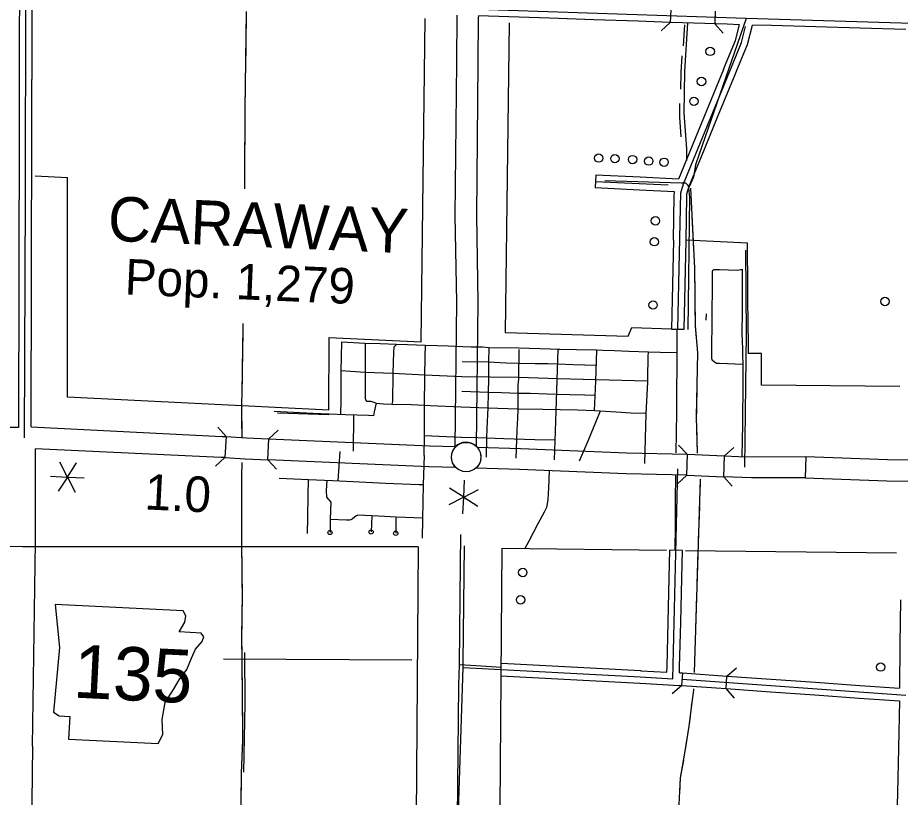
# Model space of a CAD drawing. Extents: x -4306 to 3843, y 131 to 8341.
# Drawn here: x -255 to 1424, y 2952 to 4435 of the extents above; entities that cross this region are included whole.
import ezdxf

# ---------------------------------------------------------------- set-up
doc = ezdxf.new("R2010")
doc.units = 0
for name, color, linetype in [('10', 7, 'Continuous'), ('21', 7, 'Continuous'), ('24', 7, 'Continuous'), ('31', 7, 'Continuous'), ('32', 7, 'Continuous'), ('33', 7, 'Continuous'), ('38', 7, 'Continuous'), ('52', 7, 'Continuous'), ('53', 7, 'Continuous'), ('55', 7, 'Continuous'), ('56', 7, 'Continuous'), ('57', 7, 'Continuous'), ('61', 7, 'Continuous'), ('62', 7, 'Continuous')]:
    doc.layers.add(name, color=color, linetype=linetype)

msp = doc.modelspace()

# ---------------------------------------------------------------- linework, layer by layer
at = {"layer": '10'}
for p, q in [((-252.8, 3655.5), (-600.7, 3657.9)), ((141.8, 3638.2), (139.4, 3598.3)), ((141.9, 3638.2), (180.4, 3636)), ((180.4, 3636), (222.3, 3634.2)), ((221.4, 3594.2), (223.1, 3634.1)), ((-220.3, 3437.9), (-220.6, 3615.3)), ((139.3, 3598.3), (178.3, 3596)), ((178.3, 3596), (221.6, 3594.2)), ((1018.3, 3604.8), (1017.4, 3564.8)), ((1018.8, 3604.8), (1019.4, 3604.8)), ((1019.4, 3604.8), (1088.9, 3601.8)), ((1088.1, 3561.8), (1089.8, 3601.7)), ((1244.5, 3599.9), (1243, 3559.9)), ((1244.5, 3599.9), (1243, 3559.9)), ((1018.2, 3564.8), (1087.9, 3561.8)), ((-226.6, 3049.5), (-220.3, 3437.9))]:
    msp.add_line(p, q, dxfattribs=at)
for points in [[(577.7, 4058.2), (580.3, 4349.6), (581.5, 4439.7)], [(621.4, 4434.2), (620.3, 4349.1), (617.7, 4058.9)], [(621.5, 4438.2), (621.4, 4434.2)], [(577.5, 3619.1), (580.3, 3893.9), (577.7, 4058.2)], [(617.7, 4058.9), (620.3, 3894), (617.5, 3620.2)], [(-228.8, 3656.8), (134.2, 3638.7), (141.9, 3638.2)], [(222.3, 3634.2), (529.3, 3621)], [(139.3, 3598.3), (132.1, 3598.7), (-220.6, 3615.3)], [(529.1, 3621), (578, 3619.5)], [(619.7, 3618.1), (701.5, 3615.5), (903.8, 3607.5), (1018.5, 3604.8)], [(527.6, 3581.1), (221.6, 3594.2)], [(1088.9, 3601.8), (1116.1, 3600.6)], [(1116.1, 3600.6), (1244.5, 3599.9)], [(1819.6, 3589.7), (1570.2, 3591.9), (1399.5, 3594.1), (1244.5, 3599.9)], [(577.7, 3579.5), (527.8, 3581.1)], [(1018.2, 3564.8), (1018.1, 3564.8), (902.5, 3567.5), (700, 3575.5), (617.3, 3578.2)], [(1140.7, 3560), (1087.9, 3561.8)], [(1243, 3559.9), (1140.7, 3560)], [(1243, 3559.9), (1398.5, 3554.1), (1569.7, 3551.9), (1817.9, 3549.8)], [(-226.6, 3049.5), (-229, 2837.2)]]:
    msp.add_lwpolyline(points, dxfattribs=at)
for centre, radius, start, end in [((598.1, 3598.2), 29.3, 48.5826, 134.7506), ((599.7, 3599.3), 29.6, 137.0643, 221.959), ((598.5, 3599.3), 28.3, 311.6906, 41.5462)]:
    msp.add_arc(centre, radius, start, end, dxfattribs=at)
at = {"layer": '21'}
msp.add_lwpolyline([(-183.1, 3319.2), (-174.9, 3237.4), (-186.4, 3114.7), (-175.9, 3107.4), (-155.6, 3106.4), (-157.7, 3063.1), (12.6, 3054.8), (21.6, 3072), (20.3, 3100.5), (25.9, 3132.8), (42.1, 3157.7), (52.5, 3176.2), (67, 3195.8), (76.1, 3217), (83.8, 3234.3), (96.6, 3248.6), (99.8, 3257.9), (94.7, 3264.9), (52.8, 3267), (63.2, 3285.4), (65.2, 3297.5), (60, 3307.1)], close=True, dxfattribs=at)
at = {"layer": '24'}
msp.add_circle((598.4, 3599.4), 28, dxfattribs=at)
at = {"layer": '31'}
for p, q in [((-251.3, 4474.7), (-251.4, 4402.1)), ((-227.3, 4474), (-227.4, 4402)), ((1110.5, 4391.4), (1118.2, 4421.4)), ((1121.9, 4387.6), (1129.7, 4418)), ((1133.3, 4383.8), (1142.8, 4420.7)), ((-251.4, 4402.1), (-251.6, 4317.6)), ((-227.4, 4402), (-227.6, 4317.5)), ((1092.8, 4348.6), (1110.5, 4391.4)), ((1103.9, 4344), (1121.9, 4387.6)), ((1115, 4339.4), (1133.3, 4383.8)), ((1087.6, 4336), (1092.8, 4348.6)), ((1011.3, 4118.6), (1103.9, 4344)), ((1087.6, 4336), (1087.6, 4336)), ((1109.8, 4326.9), (1115, 4339.4)), ((1022.6, 4114.6), (1045.6, 4170.6)), ((844.7, 4135.6), (843.5, 4111.6)), ((844.1, 4123.6), (982.6, 4116.8)), ((1006.2, 4101.9), (1011.3, 4118.6)), ((1018.2, 4100), (1022.6, 4114.6)), ((-240, 4096.4), (-242, 3636.2)), ((992.4, 4011.8), (994.1, 4096.2)), ((994.1, 4096.2), (994.2, 4103.8)), ((1001, 3842.6), (1006.2, 4101.9)), ((1016.4, 4011.3), (1018.1, 4095.7)), ((1018.1, 4095.7), (1018.2, 4100)), ((1054.8, 3871.6), (1054, 3859.8)), ((989, 3842.8), (1012.9, 3842.3)), ((239.5, 3683.8), (337.1, 3680.5))]:
    msp.add_line(p, q, dxfattribs=at)
for points in [[(1087.6, 4336), (1055.5, 4257.9)], [(-251.6, 4317.6), (-251.7, 4233.1)], [(-227.7, 4233), (-227.6, 4317.5)], [(1077.7, 4248.7), (1109.8, 4326.9)], [(1055.5, 4257.9), (1002.1, 4127.9)], [(1045.6, 4170.6), (1077.7, 4248.7)], [(-251.7, 4233.1), (-252.8, 3655.5)], [(-228.8, 3656.8), (-227.7, 4233)], [(929.1, 4131.5), (844.7, 4135.6)], [(1002.1, 4127.9), (929.1, 4131.5)], [(843.5, 4111.6), (927.9, 4107.5)], [(927.9, 4107.5), (994.3, 4104.3)], [(992.4, 4011.8), (990.7, 3927.3)], [(1014.7, 3926.8), (1016.4, 4011.3)], [(990.7, 3927.3), (989, 3842.8)], [(1012.9, 3842.3), (1014.7, 3926.8)], [(579.9, 2808.9), (592.5, 3199.4), (592.3, 3209.3), (595.4, 3430.4)]]:
    msp.add_lwpolyline(points, dxfattribs=at)
at = {"layer": '32'}
for p, q in [((-239.3, 4486.5), (-240, 4096.4)), ((1130.8, 4433), (602.5, 4450.9)), ((987.3, 4449.9), (986.5, 4425.9)), ((756.5, 4433.6), (621.5, 4438.2)), ((841, 4430.8), (756.5, 4433.6)), ((1130.8, 4433), (1041.4, 4175.2)), ((1071.8, 4447), (1071, 4423)), ((1446.4, 4423.8), (1130.8, 4433)), ((925.4, 4427.9), (841, 4430.8)), ((986.5, 4425.9), (925.4, 4427.9)), ((1009.9, 4425.1), (986.5, 4425.9)), ((1094.3, 4422.2), (1009.9, 4425.1)), ((1118.2, 4421.4), (1094.3, 4422.2)), ((1178.8, 4419.6), (1142.8, 4420.7)), ((1263.2, 4417.1), (1178.8, 4419.6)), ((1347.7, 4414.7), (1263.2, 4417.1)), ((1434.2, 4412.2), (1347.7, 4414.7)), ((1041.4, 4175.2), (1034.5, 4154.8)), ((1034.5, 4154.8), (1030.7, 4131.6)), ((1030.7, 4131.6), (1021.8, 4112.2)), ((1007.9, 4120.3), (862, 4124.7)), ((1016.1, 4120.1), (1007.9, 4120.3)), ((1020.2, 4115.4), (1016.1, 4120.1)), ((1021.8, 4112.2), (1020.2, 4115.4)), ((1023.3, 4093), (1021.8, 4112.2)), ((1020.6, 3842.1), (1023.3, 4093)), ((984.2, 3370), (985.4, 3422.3)), ((1009.4, 3421.7), (985.4, 3422.3)), ((1008.1, 3369.4), (1009.4, 3422)), ((982.2, 3285.5), (984.2, 3370)), ((1006.2, 3285), (1008.1, 3369.4)), ((1423.9, 3328.2), (1423.1, 3243.7)), ((980.2, 3201.1), (982.2, 3285.5)), ((1004.2, 3200.5), (1006.2, 3285)), ((1423.1, 3243.7), (1422.3, 3159.9)), ((665, 3207.6), (677.5, 3206.9)), ((677.5, 3206.9), (761.9, 3202.4)), ((761.9, 3202.4), (846.2, 3197.9)), ((846.2, 3197.9), (929.9, 3193.4)), ((929.9, 3193.4), (930.6, 3193.3)), ((930.6, 3193.3), (979.9, 3190.7)), ((979.9, 3190.7), (980.2, 3201.1)), ((1003.9, 3189.5), (1004.2, 3200.5)), ((1003.9, 3189.5), (1009.9, 3189.1)), ((1008.4, 3165.1), (1010.1, 3189.1)), ((1009.9, 3189.1), (1094.2, 3183.1)), ((664.8, 3183.5), (676.2, 3182.9)), ((676.2, 3182.9), (760.6, 3178.4)), ((760.6, 3178.4), (845, 3173.9)), ((845, 3173.9), (928.6, 3169.4)), ((1009.1, 3177.1), (1434.2, 3147)), ((1092.5, 3159.2), (1094.2, 3183.1)), ((1094.2, 3183.1), (1178.5, 3177.1)), ((1178.5, 3177.1), (1262.8, 3171.2)), ((928.6, 3169.4), (929.3, 3169.4)), ((929.3, 3169.4), (1003.3, 3165.4)), ((1003.3, 3165.5), (1008.3, 3165.1)), ((1008.2, 3165.1), (1092.5, 3159.2)), ((1092.5, 3159.2), (1176.8, 3153.2)), ((1262.8, 3171.2), (1347.1, 3165.2)), ((1347.1, 3165.2), (1422.3, 3159.9)), ((1176.8, 3153.2), (1261.1, 3147.2)), ((1261.1, 3147.2), (1345.4, 3141.3)), ((1345.4, 3141.3), (1422.1, 3135.8)), ((1422.1, 3135.8), (1420.1, 3045.8)), ((1420.1, 3045.8), (1418.2, 2961.3)), ((1418.2, 2961.3), (1416.3, 2876.8))]:
    msp.add_line(p, q, dxfattribs=at)
for points in [[(1129.5, 3992.9), (1130.7, 3833.8)], [(1130.7, 3833.8), (1129.6, 3736.4), (1127.8, 3580.1)], [(929.3, 3181.4), (991.6, 3178), (1001, 3577.3)], [(592.5, 3199.4), (929.3, 3181.4)]]:
    msp.add_lwpolyline(points, dxfattribs=at)
at = {"layer": '33'}
for p, q in [((1066.7, 3951.8), (1067.6, 3954.6)), ((1066.7, 3936.2), (1066.7, 3951.8)), ((1067.6, 3954.6), (1069.6, 3956)), ((1069.6, 3956), (1079.9, 3956.3)), ((1079.9, 3956.3), (1114.5, 3955)), ((1114.5, 3955), (1120.1, 3955.7)), ((1120.1, 3955.7), (1122.8, 3956)), ((1123.8, 3875.3), (1123.7, 3956.8)), ((1065.9, 3858.9), (1066.7, 3936.2)), ((1123, 3835.6), (1123.8, 3875.3)), ((1065.5, 3803), (1065.9, 3858.9)), ((999.4, 3775.4), (999.4, 3841.3)), ((1124.5, 3804.4), (1123, 3835.6)), ((361, 3817.6), (360.1, 3763.4)), ((406.1, 3815.4), (361, 3817.6)), ((434.6, 3814.6), (406.1, 3815.4)), ((406.1, 3815.4), (406.2, 3781.4)), ((466, 3813.7), (434.6, 3814.6)), ((466, 3813.7), (461, 3808.4)), ((486.8, 3812.7), (466, 3813.7)), ((521.1, 3811.6), (486.8, 3812.7)), ((520.3, 3790.7), (521.2, 3811.3)), ((564.4, 3810.1), (521.1, 3811.6)), ((591.3, 3809), (564.4, 3810.1)), ((460.3, 3799.6), (459.1, 3758.2)), ((461, 3808.4), (460.3, 3799.6)), ((608.1, 3808.4), (591.3, 3809)), ((629.5, 3808.6), (608.1, 3808.4)), ((641.7, 3807.3), (629.5, 3808.6)), ((641.7, 3807.3), (640.5, 3780.5)), ((698.5, 3806.3), (641.7, 3807.3)), ((698.4, 3747.7), (699.2, 3804)), ((758.3, 3804.4), (698.5, 3806.3)), ((773.3, 3803.9), (758.3, 3804.4)), ((771.6, 3745.4), (773.2, 3803.9)), ((776.7, 3804.2), (773.3, 3803.9)), ((808, 3803), (776.7, 3804.2)), ((846.2, 3802.4), (808, 3803)), ((845.1, 3743.7), (846.8, 3802.4)), ((858.4, 3802.3), (846.2, 3802.4)), ((880.5, 3801.2), (858.4, 3802.3)), ((907.5, 3800.1), (880.5, 3801.2)), ((944.9, 3798.8), (907.5, 3800.1)), ((944.4, 3791.5), (944.9, 3798.8)), ((967.4, 3798.5), (944.9, 3798.8)), ((999.4, 3797.7), (967.4, 3798.5)), ((1065.4, 3787.9), (1065.5, 3803)), ((1125.1, 3765.2), (1124.5, 3804.4)), ((406.2, 3781.4), (406.4, 3760.2)), ((519.9, 3753), (520.3, 3790.7)), ((590.7, 3781.3), (640.4, 3780.2)), ((640.4, 3780.2), (674.2, 3778.6)), ((640.5, 3780.5), (640.5, 3749.5)), ((674.2, 3778.6), (698.3, 3777.9)), ((698.3, 3777.9), (729.2, 3777)), ((729.2, 3777), (753.3, 3777.3)), ((753.3, 3777.3), (771.9, 3776.4)), ((943.7, 3748.7), (944.4, 3791.5)), ((1065.8, 3783.4), (1065.4, 3787.9)), ((1070.5, 3779.6), (1065.8, 3783.4)), ((1074.5, 3777.5), (1070.5, 3779.6)), ((1079.9, 3777.5), (1074.5, 3777.5)), ((1125, 3775.7), (1079.9, 3777.5)), ((360.1, 3763.4), (359.8, 3708.5)), ((406.4, 3760.5), (360.1, 3763.4)), ((406.4, 3760.2), (406, 3711.5)), ((459.1, 3758.2), (406.4, 3760.5)), ((771.9, 3776.4), (801.7, 3775.4)), ((801.7, 3775.4), (845.9, 3774.1)), ((999.4, 3758.1), (999.4, 3775.4)), ((1125.1, 3743.4), (1125.1, 3765.2)), ((459.1, 3758.2), (458, 3704.8)), ((520, 3754.9), (459.1, 3758.2)), ((519.4, 3696.5), (519.9, 3753)), ((590.2, 3751.8), (520, 3754.9)), ((698.6, 3750.7), (590.2, 3751.8)), ((640.5, 3749.5), (640.4, 3720.9)), ((697.3, 3736.3), (698.4, 3747.7)), ((771.7, 3748.3), (698.6, 3750.7)), ((769.4, 3686.8), (771.6, 3745.4)), ((845.2, 3746.1), (771.7, 3748.3)), ((842.2, 3687.8), (845.1, 3743.7)), ((943.6, 3743.5), (845.2, 3746.1)), ((943.6, 3741.6), (943.7, 3748.7)), ((999, 3738.5), (999.4, 3758.1)), ((1124.3, 3661.2), (1125.1, 3743.4)), ((696.9, 3689.1), (697.3, 3736.3)), ((940.3, 3681.3), (943.6, 3741.6)), ((999, 3722.6), (999, 3738.5)), ((406, 3711.5), (407.1, 3708.5)), ((589.9, 3724.6), (639.9, 3723.1)), ((640.4, 3720.9), (639.6, 3693.2)), ((639.9, 3723.1), (665.4, 3722.3)), ((665.4, 3722.3), (697, 3720.9)), ((697, 3720.9), (719.8, 3720.6)), ((719.8, 3720.6), (752.1, 3719.8)), ((752.1, 3719.8), (770, 3719.1)), ((770, 3719.1), (795.3, 3718.3)), ((795.3, 3718.3), (823.9, 3717.6)), ((823.9, 3717.6), (843.3, 3716.9)), ((998.9, 3685), (999, 3722.6)), ((359.8, 3708.5), (359.6, 3679.4)), ((407.1, 3708.5), (408.7, 3705.8)), ((408.7, 3705.8), (411, 3705.4)), ((411, 3705.4), (417.2, 3705.4)), ((417.2, 3705.4), (424.4, 3702.9)), ((427.3, 3701.6), (423.5, 3685.1)), ((424.4, 3702.9), (427.3, 3701.6)), ((427.3, 3701.6), (441, 3700.7)), ((441, 3700.7), (457.2, 3700.2)), ((458, 3704.8), (457.2, 3700.2)), ((457.2, 3700.2), (494.4, 3699.2)), ((494.4, 3699.2), (529.9, 3697.5)), ((518.8, 3636.8), (519.4, 3696.5)), ((529.9, 3697.5), (589, 3694.9)), ((589, 3694.9), (639.6, 3693.2)), ((639.6, 3693.2), (637.4, 3653.5)), ((639.6, 3693.2), (696.8, 3691.2)), ((306.8, 3682), (233, 3685.9)), ((369, 3679.8), (306.8, 3682)), ((412.6, 3678.3), (369, 3679.8)), ((383.9, 3610.7), (384.5, 3678.2)), ((422.3, 3678.1), (412.6, 3678.3)), ((423.5, 3685.1), (422.3, 3678.1)), ((696.5, 3673.5), (696.9, 3689.1)), ((696.8, 3691.2), (743.9, 3690.3)), ((743.9, 3690.3), (809.9, 3689.1)), ((767.8, 3629.6), (769.4, 3686.8)), ((809.9, 3689.1), (842.5, 3687.8)), ((840.6, 3655), (853.8, 3687.2)), ((842.5, 3687.8), (852.9, 3687.3)), ((852.9, 3687.3), (883.8, 3685.2)), ((883.8, 3685.2), (911.5, 3683.8)), ((911.5, 3683.8), (939.8, 3683)), ((938.1, 3587.4), (940.3, 3681.3)), ((998.5, 3645.2), (998.9, 3685)), ((695.1, 3650.8), (696.5, 3673.5)), ((1123.2, 3600.5), (1124.3, 3661.2)), ((637.4, 3653.5), (637.1, 3635.7)), ((694.7, 3632.1), (695.1, 3650.8)), ((830.5, 3630.4), (840.6, 3655)), ((997.9, 3607.7), (998.5, 3645.2)), ((518.2, 3602.2), (518.8, 3636.8)), ((519.4, 3640.3), (588.9, 3637.3)), ((589.5, 3637.2), (620.7, 3636.5)), ((620.7, 3636.5), (669.7, 3634.7)), ((637.1, 3635.7), (636.2, 3599.5)), ((669.7, 3634.7), (728.9, 3632.6)), ((693.6, 3597.2), (694.7, 3632.1)), ((728.9, 3632.6), (767.7, 3631.9)), ((766.4, 3594), (767.8, 3629.6)), ((814.1, 3592), (830.5, 3630.4)), ((358.1, 3610), (354.5, 3554.5)), ((518.2, 3602.2), (516.4, 3547)), ((242.5, 3559.1), (298.6, 3556.6)), ((756.4, 3573.3), (754.8, 3541.2)), ((996.6, 3565.6), (995.9, 3516.2)), ((297.7, 3556.7), (297.1, 3526.9)), ((298.6, 3556.6), (344.3, 3555)), ((333.1, 3555.4), (332.3, 3535.9)), ((344.3, 3555), (383.4, 3553.1)), ((383.4, 3553.1), (444.7, 3550.1)), ((444.7, 3550.1), (509.1, 3547.5)), ((509.1, 3547.5), (516.4, 3547)), ((516.4, 3547), (515.5, 3481.1)), ((297.1, 3526.9), (296.9, 3484.2)), ((332.3, 3535.9), (333, 3523.4)), ((754.8, 3541.2), (753.6, 3517.9)), ((333, 3523.4), (340.8, 3513.7)), ((340.8, 3513.7), (339.4, 3481.1)), ((753.6, 3517.9), (751, 3503.4)), ((995.9, 3516.2), (995.7, 3469.1)), ((746.7, 3494.9), (734.6, 3472.7)), ((751, 3503.4), (746.7, 3494.9)), ((296.9, 3484.2), (296.1, 3454.3)), ((339.4, 3481.1), (339.5, 3455.9)), ((370.6, 3479.5), (340, 3480.9)), ((376.5, 3479.4), (370.6, 3479.5)), ((379, 3479.9), (376.5, 3479.4)), ((381.7, 3481.5), (379, 3479.9)), ((386.5, 3485.6), (381.7, 3481.5)), ((389.5, 3488), (386.5, 3485.6)), ((392.6, 3488.9), (389.5, 3488)), ((419.2, 3487.4), (392.6, 3488.9)), ((419.2, 3487.4), (417.6, 3457)), ((431.8, 3487.1), (419.2, 3487.4)), ((465, 3485.2), (431.8, 3487.1)), ((464.8, 3483.6), (464.4, 3454.6)), ((515.6, 3483), (465, 3485.2)), ((515.5, 3481.1), (514.4, 3445)), ((734.6, 3472.7), (717.4, 3439.8)), ((995.7, 3469.1), (995.3, 3422.6)), ((587.5, 3452.1), (587.2, 3395.7)), ((717.4, 3439.8), (709.6, 3425.7)), ((587.2, 3395.7), (585.1, 3204.7)), ((585.2, 3204.7), (583.6, 3166.6)), ((617.6, 3202.5), (585.1, 3204.7)), ((664.9, 3199.2), (617.6, 3202.5)), ((583.6, 3166.6), (582.8, 3101.1)), ((582.8, 3101.1), (582.4, 3039.2)), ((582.4, 3039.2), (580.3, 2843.7))]:
    msp.add_line(p, q, dxfattribs=at)
for centre in [(339.5, 3455.9), (417.6, 3457), (464.4, 3454.6)]:
    msp.add_circle(centre, 4, dxfattribs=at)
at = {"layer": '38'}
msp.add_line((1008.4, 3165.1), (990.2, 3149.4), dxfattribs=at)
for points in [[(986.5, 4425.9), (969, 4409.5)], [(1087.3, 4405.5), (1071, 4423)], [(1094.2, 3183.1), (1112.4, 3198.9)], [(1108.3, 3141), (1092.5, 3159.2)]]:
    msp.add_lwpolyline(points, dxfattribs=at)
at = {"layer": '52'}
msp.add_line((136.6, 3215.9), (494.7, 3214.1), dxfattribs=at)
at = {"layer": '53'}
for p, q in [((512.6, 3818.7), (520.5, 4433)), ((680.3, 4425.2), (672.7, 3836.4)), ((-221.2, 4134.2), (-159.7, 4131.2)), ((1133.4, 4006), (1016.4, 4011.7)), ((1015.3, 3421.9), (1416.7, 3417.2))]:
    msp.add_line(p, q, dxfattribs=at)
for points in [[(337.2, 3688.8), (-159.8, 3713.1), (-159.7, 4131.2)], [(1134.7, 3833.8), (1133.4, 4006)], [(672.7, 3836.4), (906.3, 3829), (913.3, 3845.9), (989, 3843.2)], [(337.2, 3688.8), (337.8, 3827), (512.6, 3818.7)], [(1134.7, 3833.8), (1134.3, 3796.3)], [(1159.6, 3735.8), (1160.1, 3796.4), (1134.3, 3796.3)], [(1423, 3733.8), (1159.6, 3735.8)], [(506.8, 3428.7), (-245, 3428.6), (-1084.8, 3430.5)], [(506.8, 3428.7), (502.3, 2829.6)], [(658.7, 2356.3), (666.6, 3426.2)], [(666.6, 3426.2), (979.2, 3422.4)]]:
    msp.add_lwpolyline(points, dxfattribs=at)
at = {"layer": '55'}
for points in [[(176.8, 3227.8), (177.7, 3131)], [(177.7, 3131), (174.8, 3000.3)]]:
    msp.add_lwpolyline(points, dxfattribs=at)
at = {"layer": '56'}
for points in [[(180.3, 4446.2), (177.7, 4261), (176.6, 4135.8), (176.6, 4109.4)], [(180.3, 4446.2), (179.8, 4414.5)], [(1011.8, 4381.5), (1014.2, 4421.3)], [(1017.7, 4163.5), (1017.9, 4185.3), (1013.1, 4253.3), (1014.4, 4332.2), (1020, 4424.8)], [(179.5, 4393.4), (178.6, 4330)], [(1006.4, 4299.1), (1006.9, 4330.7), (1008.8, 4362.4)], [(178.3, 4308.9), (177.7, 4261), (177.5, 4245.5)], [(1007, 4208.2), (1004.3, 4245.4), (1004.8, 4271.5)], [(177.4, 4224.4), (176.9, 4161)], [(176.7, 4139.9), (176.6, 4135.8), (176.6, 4109.4)], [(1025, 4110.5), (1032.7, 3957.9), (1033.8, 3848.9), (1038.4, 3797.4)], [(1027.7, 4057.7), (1030.9, 3994.4)], [(1031.9, 3973.3), (1032.7, 3957.9), (1033.2, 3910)], [(1033.4, 3888.9), (1033.8, 3848.9), (1035.9, 3825.6)], [(172.3, 3636.3), (171.5, 3699.2), (172.2, 3723.3), (173.7, 3799.8), (174.2, 3853.6)], [(173.2, 3773.6), (173.7, 3799.8), (174, 3836.9)], [(1038.4, 3797.4), (1037.5, 3767.8), (1035.9, 3676.2), (1037.4, 3606.7)], [(1038.4, 3797.4), (1037.5, 3767.8), (1037.5, 3765.7)], [(1037.8, 3804.6), (1038.4, 3797.4)], [(171.7, 3689.1), (171.5, 3699.2), (172.2, 3723.3), (172.8, 3752.5)], [(1037.1, 3744.6), (1036, 3681.3)], [(172.3, 3636.3), (171.9, 3668)], [(1036.2, 3660.1), (1037.4, 3606.7)], [(171.8, 3589.1), (171.4, 3563.3), (171.3, 3496.1), (171, 3432.6), (172.2, 3333.7), (171.4, 3260.5), (172.2, 3153.3), (173.3, 3061.5), (170.6, 2998.5), (169.4, 2887.7), (169.9, 2831.1), (169.7, 2779.7), (168.3, 2589.1), (167.2, 2425), (167.8, 2378)], [(171.8, 3589.1), (171.4, 3563.3), (171.4, 3557.4)], [(1043.4, 3557.7), (1031.8, 3189.6)], [(1043.4, 3557.7), (1042.4, 3526.1)], [(171.4, 3536.3), (171.3, 3496.1), (171.2, 3472.9)], [(1041.7, 3504.9), (1039.7, 3441.6)], [(171.1, 3451.8), (171, 3432.6), (171.5, 3388.4)], [(1039.1, 3420.5), (1037.1, 3357.2)], [(171.8, 3367.3), (172.2, 3333.7), (171.9, 3303.9)], [(1036.4, 3336.1), (1034.4, 3272.7)], [(171.6, 3282.8), (171.4, 3260.5), (171.7, 3219.4)], [(1033.7, 3251.6), (1031.8, 3189.6)], [(171.9, 3198.3), (172.2, 3153.3), (172.4, 3134.9)], [(1030.8, 3158.8), (1030.7, 3156.5), (1027.1, 3133.1), (1021.8, 3087.5), (1013.7, 3036.4), (1005.5, 2989.4), (1003, 2938.9), (1002.7, 2821)], [(1030.8, 3158.8), (1030.7, 3156.5), (1027.1, 3133.1), (1026.4, 3127.4)], [(172.7, 3113.8), (173, 3082.1)], [(1024, 3106.4), (1021.8, 3087.5), (1014.9, 3043.7)], [(173, 3082.1), (173.3, 3061.5), (172.8, 3050.5)], [(171.9, 3029.4), (170.6, 2998.5), (170.3, 2966)], [(1011.4, 3022.9), (1005.5, 2989.4), (1004.1, 2960.1)]]:
    msp.add_lwpolyline(points, dxfattribs=at)
at = {"layer": '57'}
for centre in [(1062.3, 4370.6), (1045.8, 4313.4), (1031.4, 4275.7), (850.3, 4167.9), (881.1, 4166.7), (914.7, 4165), (945.5, 4162.2), (974.6, 4159.8), (958.1, 4048.5), (956.1, 4008.8), (953.7, 3888.5), (1394.7, 3895.1), (705.9, 3380), (701.8, 3328), (1386.5, 3200.2)]:
    msp.add_circle(centre, 8, dxfattribs=at)
at = {"layer": '61'}
for p, q in [((-160, 3561.3), (-174.6, 3589.7)), ((-160, 3561.3), (-142.7, 3588.2)), ((-192, 3562.8), (-160, 3561.3)), ((-160, 3561.3), (-177.3, 3534.4)), ((-160, 3561.3), (-128, 3559.7)), ((-160, 3561.3), (-145.4, 3532.8)), ((593.6, 3523.3), (595.1, 3555.2)), ((593.6, 3523.3), (566.7, 3540.6)), ((593.6, 3523.3), (622, 3537.9)), ((593.6, 3523.3), (565.1, 3508.6)), ((592, 3491.3), (593.6, 3523.3)), ((593.6, 3523.3), (620.5, 3505.9))]:
    msp.add_line(p, q, dxfattribs=at)
at = {"layer": '62'}
for p, q in [((140.6, 3618.3), (140.6, 3618.3)), ((222.3, 3614.1), (222.3, 3614.1)), ((1018.3, 3604.8), (1001.8, 3622.2)), ((1107.5, 3617.9), (1089.8, 3601.7)), ((1088.9, 3581.7), (1088.9, 3581.7)), ((1018.1, 3564.8), (1000.4, 3548.6)), ((1088.1, 3561.8), (1104.3, 3544.1))]:
    msp.add_line(p, q, dxfattribs=at)
for points in [[(141.8, 3638.2), (125.8, 3656.2)], [(240.8, 3650.4), (223.1, 3634.1)], [(121.5, 3582.4), (139.4, 3598.3)], [(221.4, 3594.2), (237.6, 3576.5)]]:
    msp.add_lwpolyline(points, dxfattribs=at)

# ---------------------------------------------------------------- texts
at = {"layer": '21'}
msp.add_text('135', height=101.29, rotation=357.2006, dxfattribs=at).set_placement((-150.2, 3142.3))
at = {"layer": '53'}
for s, height, p in [('CARAWAY', 84.49, (-84.1, 4010.9)), ('Pop. 1,279', 67.59, (-51.7, 3908.8))]:
    msp.add_text(s, height=height, rotation=357.5729, dxfattribs=at).set_placement(p)
at = {"layer": '61'}
msp.add_text('1.0', height=67.59, rotation=357.1416, dxfattribs=at).set_placement((-14.1, 3500.1))

doc.saveas('drawing.dxf')
